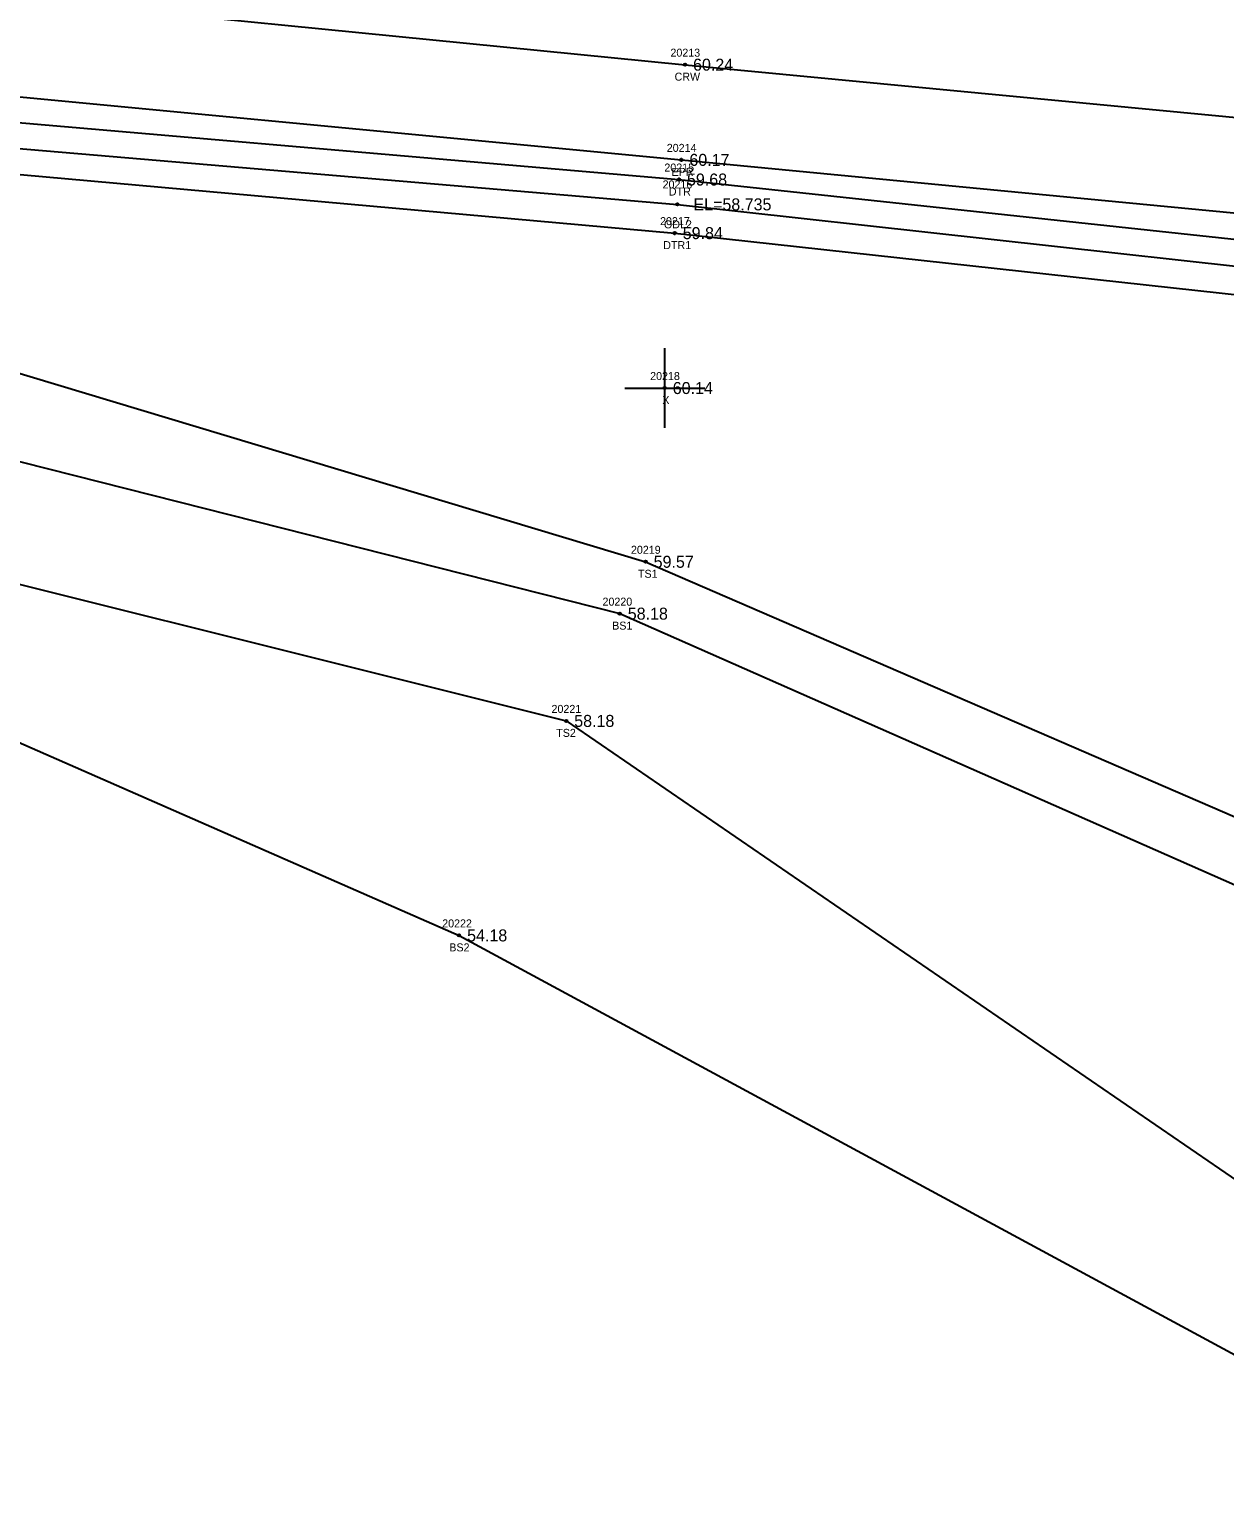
# Model space of a CAD drawing. Extents: x 2420351 to 2422725, y 845330 to 846558.
# Drawn here: x 2420818.7 to 2420968.2, y 845524.4 to 845709.7 of the extents above; entities that cross this region are included whole.
import ezdxf

# ---------------------------------------------------------------- set-up
doc = ezdxf.new("R2010")
doc.units = 0
for name, color, linetype in [('RD_DTM_BkLn1', 7, 'Continuous'), ('RD_DTM_BkLn2', 7, 'Continuous'), ('RD_DTM_BkLn_txCode', 7, 'Continuous'), ('RD_EX_H2O', 7, 'Continuous'), ('RD_EX_H2O_txCode', 7, 'Continuous'), ('RD_EX_Misc', 7, 'Continuous'), ('RD_EX_Misc_txCode', 7, 'Continuous'), ('RD_EX_Road', 7, 'Continuous'), ('RD_EX_Road_txCode', 7, 'Continuous'), ('RD_EX_TX_H2O_ELEV', 7, 'Continuous'), ('RD_EX_TX_Misc_ELEV', 7, 'Continuous'), ('RD_EX_TX_Road_ELEV', 7, 'Continuous'), ('RD_HC_Survey_ELEV', 7, 'Continuous'), ('RD_HC_Survey_txCode', 7, 'Continuous'), ('RD_SMD_Locator', 7, 'Continuous')]:
    doc.layers.add(name, color=color, linetype=linetype)

msp = doc.modelspace()

# ---------------------------------------------------------------- linework, layer by layer
at = {"layer": 'RD_DTM_BkLn1'}
msp.add_lwpolyline([(2420378.71, 845690.53), (2420439.5, 845704.09), (2420489.95, 845712.49), (2420551.89, 845719.42), (2420551.95, 845719.57), (2420607.12, 845722.67), (2420682.92, 845723.04), (2420749.65, 845719.68), (2420796.31, 845715.7), (2420900.74, 845705.33), (2421018.16, 845694.11), (2421114.61, 845684.8), (2421175.74, 845680.1), (2421234.97, 845678.35), (2421292.42, 845679.46), (2421350.56, 845683.65), (2421414.53, 845692.12), (2421472.54, 845703.63), (2421533.08, 845718.31), (2421555.4, 845725.02), (2421609.81, 845741.71), (2421666.58, 845762.88), (2421744.67, 845798.22)], dxfattribs=at)
at = {"layer": 'RD_DTM_BkLn2'}
for points in [[(2420391.68, 845656.64), (2420445.21, 845668.26), (2420499.47, 845673.15), (2420555.79, 845685.67), (2420611.25, 845685.1), (2420638.03, 845688.28), (2420664.95, 845679.28), (2420684.17, 845674.37), (2420751.52, 845659.06), (2420788.44, 845663), (2420892.57, 845636.64), (2420995.04, 845591.46), (2421010.85, 845555.52)], [(2420638.03, 845688.28), (2420664.65, 845684.42), (2420684.3, 845682.54), (2420748.92, 845680.65), (2420790.66, 845674.79), (2420895.81, 845643.13), (2420998.36, 845598.73), (2421012.82, 845561.7)], [(2420554.48, 845663.6), (2420612.71, 845664.41), (2420685.79, 845655.34), (2420750.14, 845647.33), (2420785.66, 845648.26), (2420885.87, 845623.22), (2421008.49, 845539.14)], [(2420554.18, 845658.61), (2420613.14, 845658.42), (2420684.62, 845647.43), (2420749.31, 845640.38), (2420783.25, 845635.49), (2420872.47, 845596.38), (2421005.56, 845524.43)]]:
    msp.add_lwpolyline(points, dxfattribs=at)
at = {"layer": 'RD_EX_H2O'}
for points in [[(2420681.02, 845707.72), (2420749.24, 845704.74), (2420794.5, 845700.07), (2420899.98, 845690.96), (2421017.54, 845678.31), (2421112.89, 845668.07), (2421174.6, 845666.39), (2421234.64, 845664.08), (2421293.38, 845665.28), (2421351.67, 845667.88), (2421422.34, 845677.35), (2421426.88, 845673.47), (2421424.22, 845667.22)], [(2420680.88, 845704.69), (2420749.16, 845701.08), (2420794.33, 845696.81), (2420899.79, 845687.85), (2421017.53, 845674.81), (2421112.48, 845665.13), (2421174.04, 845661.58), (2421234.82, 845660.24), (2421294.09, 845659.38), (2421352.01, 845663.24), (2421417.66, 845672.42), (2421424.72, 845673.17)], [(2420681.1, 845702.44), (2420748.92, 845698.41), (2420794.23, 845693.69), (2420899.45, 845684.25), (2421017.43, 845671.31), (2421111.87, 845660.39), (2421174.2, 845656.63), (2421235.06, 845654.38), (2421294.9, 845653.67), (2421353.19, 845655.89), (2421424.22, 845667.22)]]:
    msp.add_lwpolyline(points, dxfattribs=at)
at = {"layer": 'RD_EX_Misc'}
for p, q in [((2420898.2, 845659.87), (2420898.2, 845669.87)), ((2420893.2, 845664.87), (2420903.2, 845664.87))]:
    msp.add_line(p, q, dxfattribs=at)
at = {"layer": 'RD_EX_Road'}
msp.add_lwpolyline([(2420388.28, 845680.39), (2420441.29, 845692.04), (2420492.62, 845700.7), (2420553.92, 845707.41), (2420607.69, 845710.85), (2420682.38, 845711.26), (2420749.44, 845707.27), (2420795.12, 845703.44), (2420900.28, 845693.42), (2421017.17, 845682.19), (2421113.9, 845672.97), (2421174.87, 845668.16), (2421234.59, 845666.13), (2421293, 845667.25), (2421351.24, 845671.5), (2421419.82, 845681.17), (2421463.19, 845688.63), (2421558.82, 845713.18), (2421614.57, 845730.45), (2421670.73, 845751.42), (2421735.61, 845780.5), (2421750.75, 845787.87), (2421744.67, 845798.22), (2421739.21, 845808.11)], dxfattribs=at)
at = {"layer": 'RD_SMD_Locator'}
for centre in [(2420900.74, 845705.33), (2420900.28, 845693.42), (2420899.98, 845690.96), (2420899.79, 845687.85), (2420899.45, 845684.25), (2420898.2, 845664.87), (2420895.81, 845643.13), (2420892.57, 845636.64), (2420885.87, 845623.22), (2420872.47, 845596.38)]:
    msp.add_circle(centre, 0.15, dxfattribs=at)

# ---------------------------------------------------------------- texts
at = {"layer": 'RD_DTM_BkLn_txCode'}
for s, p in [('20219', (2420893.97, 845644.13)), ('TS1', (2420894.85, 845641.13)), ('20220', (2420890.41, 845637.64)), ('BS1', (2420891.62, 845634.64)), ('20221', (2420884.03, 845624.22)), ('TS2', (2420884.62, 845621.22)), ('20222', (2420870.35, 845597.38)), ('BS2', (2420871.24, 845594.38))]:
    msp.add_text(s, height=1, dxfattribs=at).set_placement(p)
at = {"layer": 'RD_EX_H2O_txCode'}
for s, p in [('20215', (2420898.15, 845691.96)), ('20216', (2420897.93, 845689.85)), ('DTR', (2420898.71, 845688.96)), ('20217', (2420897.61, 845685.25)), ('ODL2', (2420898.1, 845684.85)), ('DTR1', (2420898.01, 845682.25))]:
    msp.add_text(s, height=1, dxfattribs=at).set_placement(p)
at = {"layer": 'RD_EX_Misc_txCode'}
for s, p in [('20218', (2420896.37, 845665.87)), ('X', (2420897.89, 845662.87))]:
    msp.add_text(s, height=1, dxfattribs=at).set_placement(p)
at = {"layer": 'RD_EX_Road_txCode'}
for s, p in [('20214', (2420898.45, 845694.42)), ('EPR', (2420899.05, 845691.42))]:
    msp.add_text(s, height=1, dxfattribs=at).set_placement(p)
at = {"layer": 'RD_EX_TX_H2O_ELEV'}
for s, p in [('59.68', (2420900.98, 845690.21)), ('EL=58.735', (2420901.79, 845687.1)), ('59.84', (2420900.45, 845683.5))]:
    msp.add_text(s, height=1.5, dxfattribs=at).set_placement(p)
at = {"layer": 'RD_EX_TX_Misc_ELEV'}
for s, p in [('60.14', (2420899.2, 845664.12)), ('59.57', (2420896.81, 845642.38)), ('58.18', (2420893.57, 845635.89)), ('58.18', (2420886.87, 845622.47)), ('54.18', (2420873.47, 845595.63))]:
    msp.add_text(s, height=1.5, dxfattribs=at).set_placement(p)
at = {"layer": 'RD_EX_TX_Road_ELEV'}
msp.add_text('60.17', height=1.5, dxfattribs=at).set_placement((2420901.28, 845692.67))
at = {"layer": 'RD_HC_Survey_ELEV'}
msp.add_text('60.24', height=1.5, dxfattribs=at).set_placement((2420901.74, 845704.58))
at = {"layer": 'RD_HC_Survey_txCode'}
for s, p in [('20213', (2420898.91, 845706.33)), ('CRW', (2420899.43, 845703.33))]:
    msp.add_text(s, height=1, dxfattribs=at).set_placement(p)

doc.saveas('drawing.dxf')
